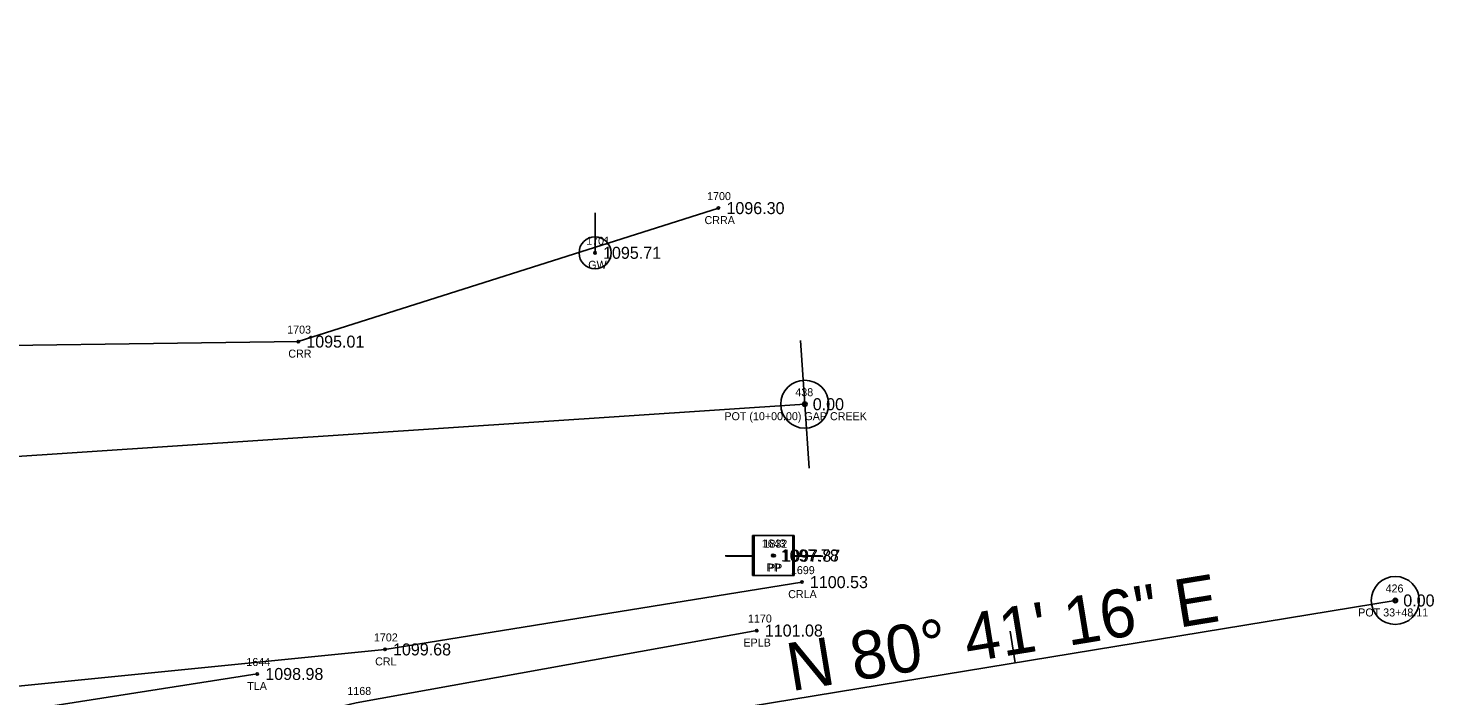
# Model space of a CAD drawing. Extents: x 1539151 to 1541799, y 1198646 to 1201165.
# Drawn here: x 1541156.3 to 1541331.9, y 1200427.6 to 1200511.1 of the extents above; entities that cross this region are included whole.
import ezdxf

# ---------------------------------------------------------------- set-up
doc = ezdxf.new("R2010")
doc.units = 0
for name, color, linetype in [('RD_EX_H2O', 7, 'Continuous'), ('RD_EX_H2O_txCode', 7, 'Continuous'), ('RD_EX_Road', 7, 'Continuous'), ('RD_EX_Road_txCode', 7, 'Continuous'), ('RD_EX_TX_H2O_ELEV', 7, 'Continuous'), ('RD_EX_TX_Road_ELEV', 7, 'Continuous'), ('RD_EX_TX_UT_ELEV', 7, 'Continuous'), ('RD_EX_TX_VEG_ELEV', 7, 'Continuous'), ('RD_EX_UT', 7, 'Continuous'), ('RD_EX_UT_txCode', 7, 'Continuous'), ('RD_EX_VEG', 7, 'Continuous'), ('RD_EX_VEG_txCode', 7, 'Continuous'), ('RD_HC_Cl', 7, 'Continuous'), ('RD_HC_Data', 7, 'Continuous'), ('RD_HC_Data_Tic', 7, 'Continuous'), ('RD_HC_Survey_ELEV', 7, 'Continuous'), ('RD_HC_txCode', 7, 'Continuous'), ('RD_SMD_Locator', 7, 'Continuous')]:
    doc.layers.add(name, color=color, linetype=linetype)

msp = doc.modelspace()

# ---------------------------------------------------------------- linework, layer by layer
at = {"layer": 'RD_EX_H2O'}
for points in [[(1541242.5, 1200488.61), (1541190.01, 1200471.92), (1541135.71, 1200471.19), (1541087.41, 1200472.32), (1541026.01, 1200483.71), (1541010.43, 1200475.64), (1540985.4, 1200459.55), (1540965.67, 1200465.48), (1540982.41, 1200511.11)], [(1541252.92, 1200441.86), (1541200.84, 1200433.45), (1541140.38, 1200427.39), (1541087.01, 1200428.4), (1541039.74, 1200441.72), (1540997.52, 1200424.93), (1540957.07, 1200418.34), (1540937.15, 1200404.81), (1540902.14, 1200374.36), (1540871.55, 1200334.52), (1540843.47, 1200300.89), (1540819.98, 1200290.97), (1540796.2, 1200252.53), (1540767.65, 1200218.32), (1540745.65, 1200154.73), (1540745.24, 1200145.69), (1540714.12, 1200111.24)]]:
    msp.add_lwpolyline(points, dxfattribs=at)
at = {"layer": 'RD_EX_Road'}
msp.add_lwpolyline([(1540705.32, 1200094.04), (1540739.01, 1200131.56), (1540770.5, 1200167.37), (1540805.54, 1200205.85), (1540841.22, 1200241.63), (1540879.37, 1200275.73), (1540919.79, 1200306.26), (1540962.73, 1200334.43), (1541008.04, 1200359.97), (1541051.86, 1200381.29), (1541099.37, 1200400.02), (1541147.99, 1200415.01), (1541197.22, 1200426.76), (1541247.29, 1200435.81)], dxfattribs=at)
at = {"layer": 'RD_EX_UT'}
for p, q in [((1541227.08, 1200483.02), (1541227.08, 1200488.02)), ((1541251.77, 1200447.7), (1541246.77, 1200447.7)), ((1541246.77, 1200447.7), (1541246.77, 1200442.7)), ((1541251.95, 1200447.67), (1541246.95, 1200447.67)), ((1541246.95, 1200447.67), (1541246.95, 1200442.67)), ((1541251.77, 1200442.7), (1541251.77, 1200447.7)), ((1541251.95, 1200442.67), (1541251.95, 1200447.67)), ((1541243.34, 1200445.14), (1541246.81, 1200445.14)), ((1541243.52, 1200445.1), (1541246.99, 1200445.1)), ((1541251.7, 1200445.14), (1541255.34, 1200445.14)), ((1541251.88, 1200445.1), (1541255.52, 1200445.1)), ((1541246.77, 1200442.7), (1541251.77, 1200442.7)), ((1541246.95, 1200442.67), (1541251.95, 1200442.67))]:
    msp.add_line(p, q, dxfattribs=at)
msp.add_circle((1541227.08, 1200483.02), 2, dxfattribs=at)
at = {"layer": 'RD_EX_VEG'}
msp.add_lwpolyline([(1541184.89, 1200430.38), (1541110.91, 1200418.83), (1540957.41, 1200347.72), (1540870.98, 1200282.61), (1540802.21, 1200226.22), (1540781.04, 1200235.77)], dxfattribs=at)
at = {"layer": 'RD_HC_Cl'}
for p, q in [((1541253.28, 1200464.1), (1540967.21, 1200445.07)), ((1541228.92, 1200423.48), (1541327.05, 1200439.57))]:
    msp.add_line(p, q, dxfattribs=at)
at = {"layer": 'RD_HC_Data'}
for centre, radius in [((1541253.28, 1200464.1), 3), ((1541253.28, 1200464.1), 0.282), ((1541327.05, 1200439.57), 3), ((1541327.05, 1200439.57), 0.282)]:
    msp.add_circle(centre, radius, dxfattribs=at)
at = {"layer": 'RD_HC_Data_Tic'}
for p, q in [((1541253.28, 1200464.1), (1541252.75, 1200472.08)), ((1541253.28, 1200464.1), (1541253.81, 1200456.12)), ((1541279.57, 1200431.79), (1541278.93, 1200435.73))]:
    msp.add_line(p, q, dxfattribs=at)
at = {"layer": 'RD_SMD_Locator'}
for centre in [(1541242.5, 1200488.61), (1541227.08, 1200483.02), (1541190.01, 1200471.92), (1541253.28, 1200464.1), (1541249.28, 1200445.19), (1541249.46, 1200445.16), (1541252.92, 1200441.86), (1541327.05, 1200439.57), (1541247.29, 1200435.81), (1541200.84, 1200433.45), (1541184.89, 1200430.38)]:
    msp.add_circle(centre, 0.15, dxfattribs=at)

# ---------------------------------------------------------------- texts
at = {"layer": 'RD_EX_H2O_txCode'}
for s, p in [('1700', (1541241.08, 1200489.61)), ('CRRA', (1541240.76, 1200486.61)), ('1703', (1541188.62, 1200472.92)), ('CRR', (1541188.76, 1200469.92)), ('1699', (1541251.55, 1200442.86)), ('CRLA', (1541251.21, 1200439.86)), ('1702', (1541199.46, 1200434.45)), ('CRL', (1541199.61, 1200431.45))]:
    msp.add_text(s, height=1, dxfattribs=at).set_placement(p)
at = {"layer": 'RD_EX_Road_txCode'}
for s, p in [('1170', (1541246.19, 1200436.81)), ('EPLB', (1541245.62, 1200433.81)), ('1168', (1541196.14, 1200427.76))]:
    msp.add_text(s, height=1, dxfattribs=at).set_placement(p)
at = {"layer": 'RD_EX_TX_H2O_ELEV'}
for s, p in [('1096.30', (1541243.5, 1200487.86)), ('1095.01', (1541191.01, 1200471.17)), ('1100.53', (1541253.92, 1200441.11)), ('1099.68', (1541201.84, 1200432.7))]:
    msp.add_text(s, height=1.5, dxfattribs=at).set_placement(p)
at = {"layer": 'RD_EX_TX_Road_ELEV'}
msp.add_text('1101.08', height=1.5, dxfattribs=at).set_placement((1541248.29, 1200435.06))
at = {"layer": 'RD_EX_TX_UT_ELEV'}
msp.add_text('1095.71', height=1.5, dxfattribs=at).set_placement((1541228.08, 1200482.27))
at = {"layer": 'RD_EX_TX_VEG_ELEV'}
msp.add_text('1098.98', height=1.5, dxfattribs=at).set_placement((1541185.89, 1200429.63))
at = {"layer": 'RD_EX_UT_txCode'}
for s, p in [('1701', (1541225.97, 1200484.02)), ('GW', (1541226.23, 1200481.02)), ('1643', (1541247.91, 1200446.19)), ('1832', (1541248.12, 1200446.16)), ('PP', (1541248.5, 1200443.19)), ('PP', (1541248.68, 1200443.16))]:
    msp.add_text(s, height=1, dxfattribs=at).set_placement(p)
at = {"layer": 'RD_EX_VEG_txCode'}
for s, p in [('1644', (1541183.52, 1200431.38)), ('TLA', (1541183.63, 1200428.38))]:
    msp.add_text(s, height=1, dxfattribs=at).set_placement(p)
at = {"layer": 'RD_HC_Data'}
msp.add_text('N 80%%d 41\' 16" E', height=6, rotation=9.3123, dxfattribs=at).set_placement((1541251.59, 1200428.21))
at = {"layer": 'RD_HC_Survey_ELEV'}
for s, p in [('0.00', (1541254.28, 1200463.35)), ('1097.78', (1541250.28, 1200444.44)), ('1097.87', (1541250.46, 1200444.41)), ('0.00', (1541328.05, 1200438.82))]:
    msp.add_text(s, height=1.5, dxfattribs=at).set_placement(p)
at = {"layer": 'RD_HC_txCode'}
for s, p in [('438', (1541252.1, 1200465.1)), ('POT (10+00.00) GAP CREEK', (1541243.24, 1200462.1)), ('426', (1541325.84, 1200440.57)), ('POT 33+48.11', (1541322.42, 1200437.57))]:
    msp.add_text(s, height=1, dxfattribs=at).set_placement(p)

doc.saveas('drawing.dxf')
